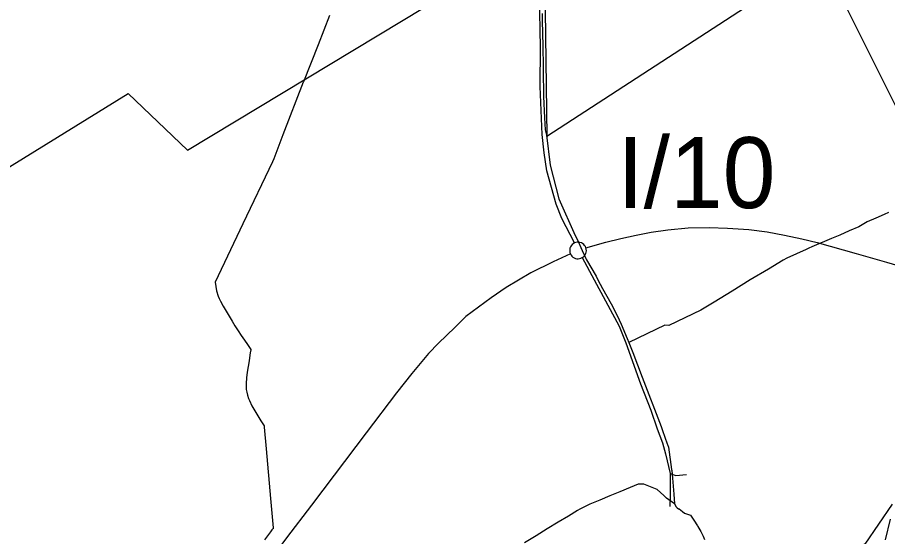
# Model space of a CAD drawing. Extents: x -789162 to -606354, y -1062736 to -945481.
# Drawn here: x -684895 to -683055, y -993607 to -992510 of the extents above; entities that cross this region are included whole.
import ezdxf

# ---------------------------------------------------------------- set-up
doc = ezdxf.new("R2010")
doc.units = 0
for name, color, linetype in [('_SIRSI VZTAHY_CYKLOTRASY MISTNI S', 7, 'Continuous'), ('_SIRSI VZTAHY_OP vodnich zdroju II stupne', 7, 'Continuous'), ('_SIRSI VZTAHY_SILNICE I a II TRIDY_STAV POPIS', 7, 'Continuous'), ('_SIRSI VZTAHY_SILNICE I TRIDY_STAV', 7, 'Continuous'), ('_SIRSI VZTAHY_SILNICE III TRIDY_STAV', 7, 'Continuous'), ('_SIRSI VZTAHY_USES_NRBK_S', 7, 'Continuous'), ('_SIRSI VZTAHY_VTL PLYNOVOD', 7, 'Continuous')]:
    doc.layers.add(name, color=color, linetype=linetype)

msp = doc.modelspace()

# ---------------------------------------------------------------- linework, layer by layer
at = {"layer": '_SIRSI VZTAHY_CYKLOTRASY MISTNI S'}
msp.add_lwpolyline([(-687456.1, -993024.3), (-687013.2, -992946.4), (-686498.6, -992862.6), (-686235.3, -993114.1), (-685816.3, -993191.9), (-685864.2, -993353.6), (-685690.7, -993455.4), (-685517.1, -993455.4), (-685433.3, -993102.1), (-685253.8, -993036.2), (-684661.3, -992670.9), (-684535.6, -992790.7), (-683781.6, -992335.6), (-683775.6, -992760.8), (-683195.1, -992383.5), (-682889.9, -992994.3), (-682866, -992760.8)], dxfattribs=at)
at = {"layer": '_SIRSI VZTAHY_OP vodnich zdroju II stupne'}
for points in [[(-683785.3, -992501.7), (-683785.3, -992516.9), (-683784.5, -992569.8), (-683783.6, -992614.8), (-683783.4, -992620.7), (-683782.9, -992677.1), (-683780.5, -992721.8), (-683779.1, -992747.1), (-683778.9, -992750.1), (-683776.6, -992758.8), (-683769, -992822.4), (-683750.3, -992893.4), (-683715.6, -992970.4), (-683711.8, -992978.7), (-683701, -993002.4), (-683693.1, -993019.6), (-683691.8, -993022.2), (-683671.8, -993057), (-683668.2, -993064.5), (-683658, -993082.8), (-683639.8, -993114.8), (-683627.1, -993140.1), (-683618.8, -993157.9), (-683606, -993188.2), (-683602.4, -993196.7), (-683594.2, -993217.8), (-683574.1, -993270), (-683533.8, -993374.5), (-683530.9, -993382.9), (-683521.1, -993410.9), (-683520.6, -993412.2), (-683518.5, -993417.8), (-683512, -993465.2), (-683511.8, -993467.6), (-683510.4, -993483.7), (-683507.4, -993517.1), (-683505.6, -993537.9), (-683502.1, -993543.9), (-683500.5, -993545.9), (-683497.6, -993548.6), (-683496, -993548.3), (-683489.1, -993553.8), (-683484.6, -993557.5), (-683471.7, -993561.8), (-683463.6, -993574), (-683458.5, -993581.8), (-683456.9, -993584.2), (-683456.2, -993585.7), (-683450.3, -993595.9), (-683447.1, -993601.8), (-683445.7, -993604.4), (-683444.9, -993606), (-683442.7, -993613)], [(-683053.3, -992922.1), (-683062.3, -992926.1), (-683080.4, -992934), (-683098.3, -992942), (-683116.2, -992952.3), (-683136.4, -992961), (-683156.6, -992969.7), (-683174.1, -992977), (-683189, -992983.3), (-683200.4, -992988.2), (-683215.5, -992994.9), (-683221.7, -992997.7), (-683227.2, -993000.3), (-683268.3, -993018.6), (-683275.9, -993023.1), (-683307, -993041.6), (-683345.5, -993064.6), (-683364.8, -993076.2), (-683384, -993088), (-683422.2, -993111.7), (-683450.3, -993128.6), (-683517.8, -993160.8), (-683526.4, -993160.1), (-683602.4, -993196.7), (-683594.2, -993217.8), (-683574.1, -993270), (-683533.8, -993374.5), (-683530.9, -993382.9), (-683521.1, -993410.9), (-683520.6, -993412.2), (-683518.5, -993417.8), (-683512, -993465.2), (-683511.8, -993467.6), (-683510.4, -993483.7), (-683507.4, -993517.1), (-683505.6, -993537.9), (-683522.5, -993525.7), (-683528.2, -993519.9), (-683542.8, -993507.5), (-683556.4, -993501.5), (-683570.5, -993496.2), (-683582.6, -993496.2), (-683599.3, -993503), (-683621.1, -993512.1), (-683642.6, -993521), (-683663.8, -993529.9), (-683684.6, -993538.5), (-683705.8, -993548.8), (-683711, -993551.7), (-683730.2, -993563.6), (-683752.1, -993576.8), (-683774.8, -993590.8), (-683798.2, -993605.4), (-683822.8, -993620.3)], [(-683059.9, -993614), (-683049, -993570)]]:
    msp.add_lwpolyline(points, dxfattribs=at)
at = {"layer": '_SIRSI VZTAHY_SILNICE I TRIDY_STAV'}
for points in [[(-683693.1, -992997), (-683650.8, -992985.1), (-683619, -992977.3), (-683586.6, -992969.8), (-683555.1, -992963.6), (-683519.9, -992958.7), (-683476.6, -992954.5), (-683432.3, -992953.8), (-683393.8, -992955.1), (-683348.9, -992958.1), (-683309.8, -992963.3), (-683273.5, -992970), (-683236.3, -992977.7), (-683203.9, -992985.4), (-683121.8, -993008.9), (-683057.7, -993027.1), (-683002.6, -993043.4)], [(-683717.4, -992986.5), (-683720, -992988), (-683722.3, -992990), (-683724.2, -992992.3), (-683725.7, -992994.9), (-683726.8, -992997.7), (-683727.3, -993000.6), (-683727.4, -993003.6), (-683726.9, -993006.6), (-683725.9, -993009.4)], [(-683693.1, -992997), (-683694.2, -992994.2), (-683695.8, -992991.7), (-683697.8, -992989.5), (-683700.2, -992987.6), (-683702.8, -992986.2), (-683705.7, -992985.3), (-683708.7, -992984.8), (-683711.7, -992984.9), (-683714.6, -992985.4), (-683717.4, -992986.5)], [(-683700.9, -993017.5), (-683698.5, -993015.8), (-683696.4, -993013.7), (-683694.7, -993011.3), (-683693.4, -993008.6), (-683692.6, -993005.8), (-683692.2, -993002.8), (-683692.4, -992999.9), (-683693.1, -992997)], [(-683725.9, -993009.4), (-683762.3, -993026.5), (-683809.9, -993049.7), (-683862.1, -993080.6), (-683893.6, -993102.3), (-683946.8, -993142.1), (-683970.5, -993164.8), (-684005.1, -993198.4), (-684026.3, -993220.1), (-684061.5, -993262), (-684093.5, -993303.3), (-684157.5, -993387.5), (-684225.7, -993476.9), (-684273.5, -993540.7), (-684326.5, -993609.6), (-684422.5, -993738.8), (-684451.5, -993776.8)], [(-683725.9, -993009.4), (-683724.5, -993012), (-683722.7, -993014.4), (-683720.5, -993016.4), (-683718, -993017.9), (-683715.2, -993019.1), (-683712.3, -993019.8), (-683709.4, -993019.9), (-683706.4, -993019.6), (-683703.6, -993018.8), (-683700.9, -993017.5)]]:
    msp.add_lwpolyline(points, dxfattribs=at)
at = {"layer": '_SIRSI VZTAHY_SILNICE III TRIDY_STAV'}
for points in [[(-683717.4, -992986.5), (-683743.8, -992934.8), (-683756.2, -992904.3), (-683775.5, -992834.3), (-683781.6, -992796.2), (-683785.7, -992757.2), (-683789.6, -992656), (-683789.4, -992573.5), (-683791.1, -992461.7)], [(-683700.9, -993017.5), (-683675.8, -993064.5), (-683622.5, -993162.5), (-683608.4, -993197.6), (-683577.4, -993283.9), (-683555.7, -993340.1), (-683542.4, -993379.4), (-683531, -993408.7), (-683524.6, -993432.4), (-683514.8, -993473.6)], [(-683514.8, -993473.6), (-683515.2, -993521.8), (-683515.8, -993543.1)], [(-683514.8, -993473.6), (-683503.1, -993477.8), (-683480.3, -993475.6)]]:
    msp.add_lwpolyline(points, dxfattribs=at)
at = {"layer": '_SIRSI VZTAHY_USES_NRBK_S'}
msp.add_lwpolyline([(-683045.5, -993538.1), (-683103.1, -993623.1), (-683453.6, -993841.8), (-683573.5, -994016.4), (-683653.9, -994166.7), (-683778.3, -994320), (-683946.7, -994477.9), (-684040.8, -994600.9), (-684107.6, -994682.9), (-684250.2, -994957.7), (-684321.5, -995221.9), (-684408, -995446.6), (-684520.2, -995566.6), (-684652.2, -995650.1), (-684800.9, -995719.9)], dxfattribs=at)
at = {"layer": '_SIRSI VZTAHY_VTL PLYNOVOD'}
for points in [[(-684235.4, -992505.7), (-684259.5, -992567.5), (-684290.3, -992645.9), (-684290.7, -992647), (-684334, -992758.2), (-684353.3, -992808.5), (-684355.9, -992814.9), (-684418.5, -992946.2), (-684477.1, -993069.3), (-684474.2, -993087.4), (-684470.7, -993098.6), (-684468.4, -993104.1), (-684465.6, -993109.8), (-684460, -993120.2), (-684453.7, -993130.9), (-684447.6, -993141.2), (-684441.4, -993151.8), (-684435.3, -993161.6), (-684428.6, -993172), (-684422, -993181.8), (-684415.2, -993191.8), (-684408.5, -993201.3), (-684401.6, -993211.3), (-684401.8, -993212.3), (-684401.8, -993212.5), (-684402.7, -993218.3), (-684403.5, -993223.6), (-684405.3, -993235.8), (-684407.4, -993247.8), (-684409.3, -993259.3), (-684410.7, -993271.5), (-684411.5, -993283.8), (-684411.3, -993295.8), (-684410.8, -993299), (-684410.3, -993302), (-684408.9, -993307.9), (-684406.5, -993314.9), (-684404.6, -993319.5), (-684399.2, -993330.5), (-684393.5, -993341.2), (-684387.1, -993351.9), (-684380.6, -993362.4), (-684373.5, -993373.1), (-684373.5, -993373.2), (-684373.3, -993375.5), (-684369.5, -993421.3), (-684369.5, -993421.7), (-684360.1, -993526.6), (-684354.7, -993588.1), (-684354.6, -993589.6)], [(-684354.6, -993589.6), (-684356.9, -993592.6), (-684360.1, -993596.7), (-684373, -993613.8)], [(-684354.6, -993589.6), (-684354.6, -993590.5)]]:
    msp.add_lwpolyline(points, dxfattribs=at)

# ---------------------------------------------------------------- texts
at = {"layer": '_SIRSI VZTAHY_SILNICE I a II TRIDY_STAV POPIS'}
msp.add_text('I/10', height=150, dxfattribs=at).set_placement((-683626.9, -992912.9))

doc.saveas('drawing.dxf')
